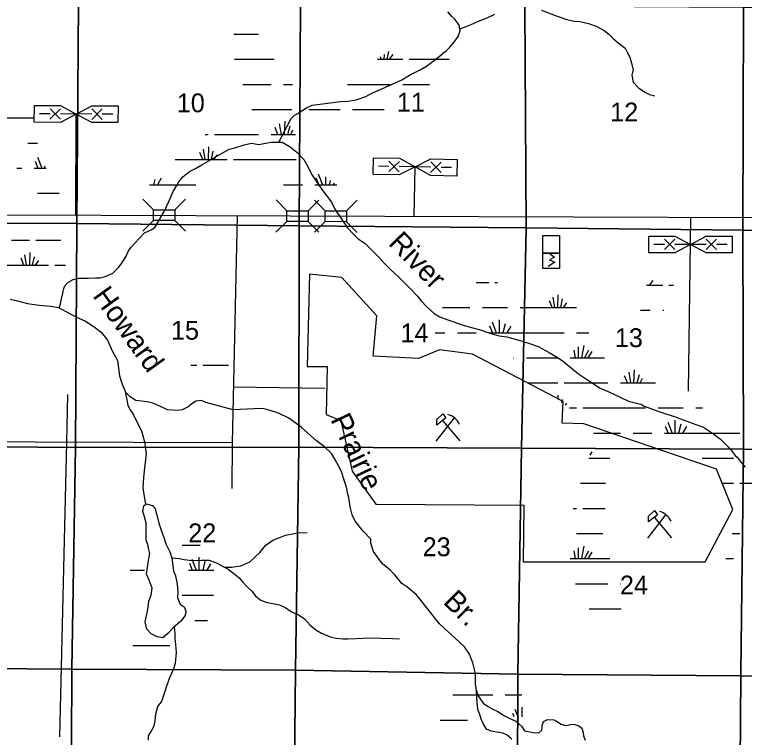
# Model space of a CAD drawing. Extents: x 380424 to 701066, y 1117407 to 1412949.
# Drawn here: x 588826 to 606273, y 1213175 to 1230454 of the extents above; entities that cross this region are included whole.
import ezdxf

# ---------------------------------------------------------------- set-up
doc = ezdxf.new("R2010")
doc.units = 0
for name, color, linetype in [('Bridges and Drawbridges State Highways', 7, 'Continuous'), ('Culture', 7, 'Continuous'), ('Intermittent Ponds', 7, 'Continuous'), ('Lakes and Ponds', 7, 'Continuous'), ('Local Roads Improved', 7, 'Continuous'), ('Local Roads Paved', 7, 'Continuous'), ('Local Roads Related Cells', 7, 'Continuous'), ('Narrow River Creek and Branch and Slough', 7, 'Continuous'), ('Narrow River Creek and Branch and Slough Text', 7, 'Continuous'), ('Section Lines', 7, 'Continuous'), ('Section Numbers', 7, 'Continuous'), ('State Routes Highway Center Lines', 7, 'Continuous'), ('Strip Mining Area', 7, 'Continuous'), ('Swamps', 7, 'Continuous'), ('Township  and Range lines', 7, 'Continuous')]:
    doc.layers.add(name, color=color, linetype=linetype)

msp = doc.modelspace()

# ---------------------------------------------------------------- linework, layer by layer
at = {"layer": 'Bridges and Drawbridges State Highways'}
for p, q in [((592146, 1225786), (591890, 1226042)), ((592658, 1225786), (592914, 1226042)), ((595332, 1225765), (595077, 1226022)), ((595844, 1225763), (596101, 1226018)), ((596250, 1225761), (595995, 1226018)), ((596762, 1225760), (597019, 1226015)), ((592146, 1225530), (591890, 1225274)), ((592658, 1225530), (592914, 1225274)), ((595331, 1225509), (595074, 1225254)), ((595843, 1225507), (596098, 1225250)), ((596249, 1225505), (595992, 1225250)), ((596761, 1225504), (597016, 1225247))]:
    msp.add_line(p, q, dxfattribs=at)
for points in [[(592146, 1225786), (592658, 1225786), (592658, 1225530), (592146, 1225530)], [(595332, 1225765), (595844, 1225763), (595843, 1225507), (595331, 1225509)], [(596250, 1225761), (596762, 1225760), (596761, 1225504), (596249, 1225505)]]:
    msp.add_lwpolyline(points, close=True, dxfattribs=at)
at = {"layer": 'Culture'}
for p, q in [((601452, 1224382), (601452, 1224753)), ((601452, 1224753), (601853, 1224753)), ((601853, 1224753), (601853, 1224382)), ((601853, 1224382), (601452, 1224382)), ((598902, 1220253), (599339, 1220812)), ((599058, 1220754), (599471, 1220261)), ((603961, 1217936), (604398, 1218495)), ((604117, 1218437), (604530, 1217944))]:
    msp.add_line(p, q, dxfattribs=at)
for points in [[(601853, 1224753), (601452, 1224753), (601452, 1225172), (601853, 1225172)], [(599064, 1220913), (599134, 1220814), (598919, 1220642), (598919, 1220777)], [(604123, 1218596), (604193, 1218497), (603978, 1218325), (603978, 1218460)]]:
    msp.add_lwpolyline(points, close=True, dxfattribs=at)
msp.add_lwpolyline([(601608, 1224753), (601729, 1224659), (601617, 1224591), (601738, 1224532), (601582, 1224432)], dxfattribs=at)
for centre in [(599068, 1220480), (604127, 1218163)]:
    msp.add_arc(centre, 431, 24.5415, 74.8304, dxfattribs=at)
at = {"layer": 'Intermittent Ponds'}
msp.add_lwpolyline([(600712, 1213137), (600602, 1213226), (600497, 1213278), (600356, 1213299), (600219, 1213325), (600109, 1213373), (600035, 1213488), (599978, 1213609), (599946, 1213724), (599899, 1213840), (599889, 1213934), (599883, 1213997), (599868, 1214302), (599878, 1214260), (599915, 1214155), (599920, 1214144), (600025, 1213992), (600130, 1213918), (600240, 1213861), (600377, 1213793), (600539, 1213688), (600649, 1213635), (600807, 1213562), (600943, 1213441), (601017, 1213336), (601221, 1213289), (601358, 1213284), (601426, 1213346), (601437, 1213394), (601437, 1213462), (601468, 1213556), (601563, 1213604), (601715, 1213598), (601778, 1213562), (601893, 1213488), (601993, 1213457), (602056, 1213467), (602119, 1213483), (602192, 1213488), (602313, 1213451), (602387, 1213399), (602418, 1213289), (602428, 1213215), (602465, 1213110)], dxfattribs=at)
at = {"layer": 'Lakes and Ponds'}
msp.add_lwpolyline([(591982, 1217081), (592029, 1217401), (592056, 1217574), (592024, 1217700), (592008, 1217789), (591972, 1217889), (591972, 1218304), (591919, 1218503), (591888, 1218587), (591919, 1218708), (591972, 1218760), (592124, 1218718), (592187, 1218640), (592239, 1218435), (592276, 1218293), (592323, 1218151), (592397, 1217957), (592439, 1217800), (592533, 1217611), (592586, 1217464), (592607, 1217286), (592628, 1217149), (592670, 1217034), (592712, 1216840), (592727, 1216656), (592722, 1216509), (592780, 1216362), (592880, 1216294), (592916, 1216194), (592906, 1216089), (592801, 1215953), (592607, 1215785), (592491, 1215659), (592371, 1215559), (592234, 1215580), (592087, 1215654), (591987, 1215764), (591945, 1215937), (592014, 1216231), (592035, 1216430), (592092, 1216572), (592113, 1216745), (592045, 1216934)], close=True, dxfattribs=at)
at = {"layer": 'Local Roads Improved'}
for points in [[(590293, 1225655), (590298, 1228076)], [(598374, 1225626), (598398, 1226813)], [(590090, 1221370), (590064, 1220229)], [(594030, 1220213), (594017, 1219124)]]:
    msp.add_lwpolyline(points, dxfattribs=at)
at = {"layer": 'Local Roads Paved'}
for points in [[(594146, 1225641), (594030, 1220213), (584600, 1220250), (584573, 1217567), (580552, 1217530), (580478, 1214990), (581912, 1214974), (581785, 1204105)], [(604933, 1221456), (604994, 1225603)], [(594058, 1221553), (596248, 1221524)], [(590064, 1220229), (589902, 1213187)]]:
    msp.add_lwpolyline(points, dxfattribs=at)
at = {"layer": 'Local Roads Related Cells'}
for p, q in [((589297, 1227881), (589299, 1228281)), ((589299, 1228281), (589924, 1228278)), ((589924, 1228278), (590298, 1228076)), ((590298, 1228076), (590674, 1228274)), ((590674, 1228274), (591299, 1228271)), ((591299, 1228271), (591297, 1227871)), ((589672, 1227954), (589923, 1228203)), ((589922, 1227953), (589673, 1228204)), ((590672, 1227949), (590923, 1228198)), ((590922, 1227950), (590673, 1228201)), ((589673, 1228079), (589423, 1228081)), ((590298, 1228076), (589922, 1227878)), ((590673, 1228074), (589923, 1228078)), ((590672, 1227874), (590298, 1228076)), ((591173, 1228072), (590923, 1228073)), ((589922, 1227878), (589297, 1227881)), ((591297, 1227871), (590672, 1227874)), ((597394, 1226633), (597402, 1227033)), ((597402, 1227033), (598027, 1227020)), ((597770, 1226701), (598025, 1226945)), ((598020, 1226696), (597775, 1226950)), ((598027, 1227020), (598398, 1226813)), ((598398, 1226813), (598777, 1227005)), ((598770, 1226681), (599025, 1226925)), ((599020, 1226678), (598775, 1226933)), ((598777, 1227005), (599402, 1226993)), ((599402, 1226993), (599394, 1226593)), ((597773, 1226825), (597523, 1226830)), ((598398, 1226813), (598019, 1226621)), ((598773, 1226805), (598023, 1226820)), ((598769, 1226606), (598398, 1226813)), ((599273, 1226795), (599023, 1226800)), ((598019, 1226621), (597394, 1226633)), ((599394, 1226593), (598769, 1226606)), ((603984, 1225160), (604609, 1225160)), ((603984, 1224760), (603984, 1225160)), ((604609, 1225160), (604984, 1224960)), ((604984, 1224960), (605359, 1225160)), ((605359, 1225160), (605984, 1225160)), ((605984, 1225160), (605984, 1224760)), ((604359, 1224960), (604109, 1224960)), ((604359, 1224835), (604609, 1225085)), ((604609, 1224835), (604359, 1225085)), ((604984, 1224960), (604609, 1224760)), ((605359, 1224960), (604609, 1224960)), ((605359, 1224760), (604984, 1224960)), ((605609, 1224837), (605359, 1225087)), ((605359, 1224835), (605609, 1225085)), ((605859, 1224960), (605609, 1224960)), ((604609, 1224760), (603984, 1224760)), ((605984, 1224760), (605359, 1224760))]:
    msp.add_line(p, q, dxfattribs=at)
at = {"layer": 'Narrow River Creek and Branch and Slough'}
for points in [[(601424, 1230559), (601771, 1230422), (602029, 1230338), (602202, 1230301), (602339, 1230286), (602549, 1230238), (602728, 1230181), (602923, 1230075), (603028, 1229986), (603133, 1229886), (603254, 1229781), (603422, 1229655), (603464, 1229571), (603533, 1229434), (603575, 1229292), (603611, 1229145), (603585, 1229003), (603617, 1228835), (603738, 1228703), (603890, 1228598), (604006, 1228540), (604132, 1228509)], [(595146, 1227404), (595436, 1227967), (595520, 1228051), (595578, 1228083), (595631, 1228114), (595804, 1228225), (595941, 1228288), (596619, 1228377), (596803, 1228382), (596992, 1228419), (597224, 1228498), (597366, 1228577), (597571, 1228666), (597691, 1228719), (597923, 1228819), (598086, 1228898), (598307, 1229034), (598391, 1229066), (598522, 1229134), (598669, 1229224), (598801, 1229318), (598895, 1229392), (599027, 1229492), (599148, 1229592), (599237, 1229686), (599327, 1229786), (599426, 1229928), (599474, 1230065), (599453, 1230202), (599348, 1230343), (599279, 1230412), (599179, 1230522)], [(599466, 1230116), (599621, 1230170), (599742, 1230217), (599915, 1230301), (600126, 1230375), (600310, 1230464)], [(589891, 1223447), (589922, 1223536), (589949, 1223662), (589980, 1223794), (590001, 1223910), (590027, 1223973), (590096, 1224052), (590227, 1224120), (590353, 1224157), (590474, 1224157), (590585, 1224157), (590758, 1224162), (590863, 1224162), (590990, 1224193), (591174, 1224272), (591310, 1224409), (591389, 1224514), (591494, 1224682), (591552, 1224809), (591610, 1224893), (591689, 1224982), (591933, 1225240), (592090, 1225312), (592180, 1225368), (592426, 1225785), (592460, 1225869), (592518, 1226001), (592565, 1226111), (592618, 1226227), (592686, 1226348), (592755, 1226453), (592849, 1226574), (593007, 1226700), (593149, 1226774), (593301, 1226863), (593522, 1226994), (593733, 1227110), (593953, 1227236), (594090, 1227268), (594311, 1227341), (594490, 1227378), (594668, 1227352), (594952, 1227404), (595226, 1227404), (595410, 1227294), (595573, 1227163), (595741, 1226994), (595841, 1226810), (595925, 1226637), (596067, 1226421), (596172, 1226274), (596277, 1226137), (596403, 1225974), (596477, 1225817), (596517, 1225758), (596787, 1225359), (596929, 1225207), (597040, 1225091), (597208, 1224986), (597534, 1224655), (597649, 1224518), (597807, 1224366), (598007, 1224182), (598301, 1223892), (598454, 1223724), (598548, 1223614), (598669, 1223477), (598853, 1223309), (598990, 1223230), (599158, 1223162), (599300, 1223120), (599526, 1223036), (599747, 1222972), (599931, 1222925), (600184, 1222841), (600410, 1222778), (600594, 1222752), (600935, 1222652), (601182, 1222578), (601340, 1222520), (601608, 1222373), (601798, 1222263), (601950, 1222158), (602139, 1222005), (602308, 1221868), (602523, 1221726), (602823, 1221521), (603017, 1221448), (603301, 1221306), (603501, 1221216), (603753, 1221148), (603801, 1221138), (603864, 1221101), (604011, 1221043), (604227, 1220964), (604421, 1220901), (604600, 1220848), (604721, 1220796), (604921, 1220728), (605115, 1220654), (605294, 1220591), (605536, 1220433), (605704, 1220302), (605846, 1220160), (605930, 1220070), (606051, 1219918), (606103, 1219871), (606193, 1219750), (606293, 1219639)], [(588722, 1223649), (588896, 1223612), (589138, 1223549), (589411, 1223507), (589695, 1223481), (589879, 1223454), (590052, 1223355), (590184, 1223281), (590363, 1223197), (590520, 1223129), (590725, 1222992), (590894, 1222860), (591046, 1222671), (591167, 1222398), (591283, 1222182), (591335, 1221819), (591398, 1221620), (591472, 1221451), (591530, 1221120), (591572, 1221031), (591666, 1220889), (591766, 1220689), (591856, 1220505), (591935, 1220240), (591973, 1219956), (591951, 1219746), (591925, 1219546), (591904, 1219378), (591894, 1219146), (591915, 1218983), (591917, 1218979), (591959, 1218747)], [(599868, 1214302), (599841, 1214454), (599841, 1214700), (599784, 1214958), (599700, 1215162), (599584, 1215341), (599348, 1215556), (599122, 1215760), (598986, 1215892), (598766, 1216165), (598535, 1216458), (598424, 1216590), (598204, 1216773), (598083, 1216857), (597915, 1217062), (597805, 1217172), (597622, 1217324), (597506, 1217477), (597406, 1217623), (597343, 1217818), (597338, 1217917), (597165, 1218096), (597097, 1218185), (596966, 1218348), (596892, 1218495), (596845, 1218684), (596813, 1218914), (596787, 1219019), (596766, 1219124), (596719, 1219277), (596630, 1219544), (596477, 1219843), (596399, 1219959), (596226, 1220132), (596042, 1220263), (595837, 1220447), (595675, 1220594), (595381, 1220809), (595134, 1220924), (594914, 1220998), (594756, 1221035), (594552, 1221029), (594052, 1221005), (593396, 1221183), (593291, 1221230), (593155, 1221210), (593055, 1221141), (592976, 1221078), (592835, 1221005), (592730, 1220989), (592483, 1221005), (592315, 1221084), (592131, 1221168), (591995, 1221194), (591859, 1221210), (591727, 1221225), (591591, 1221320), (591476, 1221427)], [(593852, 1217241), (594009, 1217247), (594235, 1217279), (594451, 1217373), (594687, 1217599), (594829, 1217773), (595003, 1217894), (595181, 1217962), (595302, 1218010), (595633, 1218073), (595823, 1218062)], [(592583, 1217471), (592756, 1217448), (592882, 1217432), (593066, 1217406), (593292, 1217416), (593476, 1217411), (593665, 1217343), (593813, 1217264), (593928, 1217196), (594070, 1217091), (594186, 1216996), (594275, 1216896), (594380, 1216786), (594501, 1216670), (594575, 1216565), (594696, 1216465), (594833, 1216407), (595158, 1216344), (595311, 1216270), (595458, 1216170), (595605, 1216113), (595753, 1216013), (595889, 1215860), (596031, 1215750), (596163, 1215666), (596368, 1215576), (596515, 1215545), (596678, 1215529), (596804, 1215529), (596993, 1215540), (597304, 1215555), (597871, 1215540), (598029, 1215534)], [(592028, 1213113), (592028, 1213212), (592091, 1213318), (592165, 1213449), (592186, 1213575), (592202, 1213738), (592249, 1213912), (592338, 1214027), (592375, 1214138), (592428, 1214280), (592464, 1214411), (592538, 1214606), (592627, 1214800), (592669, 1214947), (592696, 1215205), (592680, 1215400), (592664, 1215542), (592664, 1215662), (592649, 1215821)]]:
    msp.add_lwpolyline(points, dxfattribs=at)
at = {"layer": 'Section Lines'}
for points in [[(590354, 1230726), (590354, 1230713), (590316, 1225459), (584947, 1225482), (584988, 1230777), (590334, 1230727)], [(595661, 1230692), (595626, 1225416), (595626, 1225407), (590323, 1225459), (590316, 1225459), (590354, 1230713), (590354, 1230726)], [(601027, 1230664), (601027, 1230646), (601059, 1225354), (595626, 1225407), (595626, 1225416), (595661, 1230692), (595676, 1230692)], [(606248, 1230633), (606248, 1230626), (606236, 1225303), (601059, 1225354), (601027, 1230646), (601027, 1230664)], [(611856, 1230581), (611856, 1230571), (611837, 1225330), (611840, 1225292), (606258, 1225303), (606236, 1225303), (606248, 1230626), (606248, 1230633), (611846, 1230581)], [(590316, 1225459), (590316, 1225426), (590282, 1220107), (590268, 1220107), (584902, 1220152), (584895, 1220152), (584895, 1220166), (584946, 1225472), (584947, 1225482)], [(595626, 1225407), (595618, 1220117), (590282, 1220107), (590316, 1225426), (590316, 1225459), (590323, 1225459)], [(601059, 1225354), (601059, 1225331), (600943, 1220092), (595618, 1220117), (595626, 1225407)], [(606236, 1225303), (606236, 1225278), (606252, 1220073), (606252, 1220063), (600943, 1220092), (601059, 1225331), (601059, 1225354)], [(611840, 1225292), (611868, 1220018), (606271, 1220063), (606252, 1220063), (606252, 1220073), (606236, 1225278), (606236, 1225303), (606258, 1225303)], [(590282, 1220107), (590282, 1220103), (590192, 1214804), (584853, 1214848), (584895, 1220152), (584902, 1220152), (590268, 1220107)], [(595618, 1220117), (595543, 1214785), (590207, 1214803), (590192, 1214804), (590282, 1220103), (590282, 1220107)], [(600943, 1220092), (600854, 1214688), (600854, 1214684), (595543, 1214785), (595618, 1220117)], [(606252, 1220063), (606191, 1214707), (606191, 1214649), (600854, 1214684), (600854, 1214688), (600943, 1220092)], [(611868, 1220018), (611870, 1214702), (611870, 1214647), (608875, 1214632), (606191, 1214649), (606191, 1214707), (606252, 1220063), (606271, 1220063)], [(590192, 1214804), (590192, 1214786), (590168, 1209527), (590168, 1209522), (590161, 1209522), (584812, 1209549), (584853, 1214848)], [(595543, 1214785), (595543, 1214763), (595483, 1209507), (590168, 1209522), (590168, 1209527), (590192, 1214786), (590192, 1214804), (590207, 1214803)], [(600854, 1214684), (600837, 1209483), (595488, 1209507), (595483, 1209507), (595543, 1214763), (595543, 1214785)], [(606191, 1214649), (606147, 1209426), (600837, 1209483), (600854, 1214684)], [(611870, 1214647), (611802, 1209383), (606157, 1209426), (606147, 1209426), (606191, 1214649), (608875, 1214632)]]:
    msp.add_lwpolyline(points, close=True, dxfattribs=at)
at = {"layer": 'State Routes Highway Center Lines'}
msp.add_lwpolyline([(640551, 1225621), (608969, 1225590), (572811, 1225715), (567889, 1228370), (547875, 1228304), (542500, 1228290), (542132, 1228289), (536228, 1228275), (533934, 1228260), (532069, 1228431), (531223, 1228480), (521382, 1228594), (519319, 1228617), (515590, 1228660)], dxfattribs=at)
at = {"layer": 'Strip Mining Area'}
for p, q in [((595879, 1224248), (595816, 1222042)), ((596649, 1224167), (595879, 1224248)), ((597482, 1223251), (596649, 1224167)), ((597399, 1222292), (597482, 1223251)), ((598981, 1222438), (598481, 1222230)), ((599772, 1222334), (598981, 1222438)), ((601938, 1221209), (599772, 1222334)), ((598481, 1222230), (597399, 1222292)), ((595816, 1222042), (596295, 1222042)), ((596295, 1222042), (596274, 1220897)), ((601917, 1220688), (601938, 1221209)), ((596274, 1220897), (596628, 1220751)), ((596628, 1220751), (596899, 1219543)), ((602437, 1220668), (601917, 1220688)), ((605602, 1219584), (602437, 1220668)), ((596899, 1219543), (597461, 1218751)), ((605998, 1218626), (605602, 1219584)), ((597461, 1218751), (601001, 1218730)), ((601001, 1218730), (600980, 1217376)), ((605331, 1217376), (605998, 1218626)), ((600980, 1217376), (605331, 1217376))]:
    msp.add_line(p, q, dxfattribs=at)
at = {"layer": 'Swamps'}
for p, q in [((597792, 1229387), (597876, 1229500)), ((597357, 1228787), (597807, 1228787)), ((595857, 1228187), (596607, 1228187)), ((596907, 1228187), (597357, 1228187)), ((597357, 1228187), (597657, 1228187)), ((595122, 1227587), (595057, 1227759)), ((595207, 1227587), (595161, 1227842)), ((595278, 1227587), (595295, 1227903)), ((595355, 1227587), (595413, 1227791)), ((593607, 1227587), (594657, 1227587)), ((595431, 1227587), (595480, 1227696)), ((593385, 1226987), (593345, 1227240)), ((593463, 1226987), (593469, 1227291)), ((593322, 1226988), (593256, 1227161)), ((593530, 1226987), (593573, 1227193)), ((593592, 1226987), (593676, 1227100)), ((589314, 1226949), (589385, 1226783)), ((593157, 1226987), (593907, 1226987)), ((594057, 1226987), (595557, 1226987)), ((592333, 1226541), (592243, 1226387)), ((596026, 1226553), (596097, 1226387)), ((595257, 1226387), (595707, 1226387)), ((588884, 1225061), (589184, 1225061)), ((589049, 1224462), (588983, 1224634)), ((589112, 1224461), (589072, 1224714)), ((589190, 1224461), (589196, 1224764)), ((589257, 1224461), (589300, 1224666)), ((588884, 1224461), (589634, 1224461)), ((589319, 1224460), (589403, 1224574)), ((601816, 1223450), (601822, 1223754)), ((601738, 1223450), (601698, 1223703)), ((601883, 1223450), (601926, 1223656)), ((601945, 1223449), (602029, 1223563)), ((600010, 1223450), (600610, 1223450)), ((601510, 1223450), (602260, 1223450)), ((600239, 1223113), (600342, 1222850)), ((600408, 1223161), (600408, 1222850)), ((600553, 1223064), (600500, 1222850)), ((600179, 1223016), (600250, 1222850)), ((600686, 1223004), (600597, 1222850)), ((599410, 1222850), (599860, 1222850)), ((600160, 1222850), (601510, 1222850)), ((601510, 1222850), (601960, 1222850)), ((602301, 1222508), (602301, 1222250)), ((602434, 1222545), (602375, 1222250)), ((602192, 1222436), (602229, 1222250)), ((602542, 1222424), (602448, 1222249)), ((602627, 1222400), (602528, 1222251)), ((601060, 1222250), (601510, 1222250)), ((601510, 1222250), (601810, 1222250)), ((603475, 1221650), (603410, 1221822)), ((603560, 1221650), (603514, 1221904)), ((603631, 1221650), (603648, 1221966)), ((603708, 1221650), (603766, 1221854)), ((601510, 1221650), (601810, 1221650)), ((601960, 1221650), (603010, 1221650)), ((603784, 1221650), (603833, 1221759)), ((602410, 1221050), (603910, 1221050)), ((604210, 1221050), (604810, 1221050)), ((604379, 1220616), (604450, 1220450)), ((604439, 1220713), (604542, 1220450)), ((604608, 1220761), (604608, 1220450)), ((604753, 1220664), (604700, 1220450)), ((604886, 1220604), (604796, 1220450)), ((603610, 1220450), (604060, 1220450)), ((604360, 1220450), (605710, 1220450)), ((605710, 1220450), (606160, 1220450)), ((605260, 1219850), (605710, 1219850)), ((605710, 1219850), (606010, 1219850)), ((606160, 1219250), (607210, 1219250)), ((602192, 1217636), (602229, 1217450)), ((602301, 1217708), (602301, 1217450)), ((602434, 1217745), (602375, 1217450)), ((602542, 1217624), (602448, 1217449)), ((593232, 1217484), (593232, 1217173)), ((602627, 1217600), (602528, 1217451)), ((593003, 1217339), (593073, 1217173)), ((593063, 1217435), (593166, 1217173)), ((593377, 1217387), (593324, 1217173)), ((593510, 1217327), (593420, 1217173)), ((592834, 1216573), (593584, 1216573)), ((593134, 1215973), (593434, 1215973))]:
    msp.add_line(p, q, dxfattribs=at)
for points in [[(594069, 1229987), (594657, 1229987)], [(597663, 1229387), (597665, 1229502)], [(597730, 1229387), (597769, 1229572)], [(594081, 1229387), (595028, 1229387)], [(597502, 1229387), (598107, 1229387)], [(597522, 1229388), (597518, 1229400)], [(597585, 1229387), (597576, 1229442)], [(598257, 1229387), (599218, 1229387)], [(594282, 1228787), (594957, 1228787)], [(595257, 1228787), (595472, 1228787)], [(596784, 1228787), (597357, 1228787)], [(598107, 1228787), (598747, 1228787)], [(594495, 1228187), (595457, 1228187)], [(588568, 1227983), (589295, 1227983)], [(593385, 1227587), (593457, 1227587)], [(594957, 1227587), (595540, 1227587)], [(589145, 1227383), (589371, 1227383)], [(589375, 1227046), (589478, 1226783)], [(592662, 1226987), (593157, 1226987)], [(588878, 1226783), (588995, 1226783)], [(589295, 1226783), (589577, 1226783)], [(589544, 1226833), (589544, 1226783)], [(596086, 1226650), (596189, 1226387)], [(596255, 1226572), (596255, 1226387)], [(592050, 1226387), (593157, 1226387)], [(592055, 1226392), (592055, 1226387)], [(592178, 1226514), (592147, 1226387)], [(596007, 1226387), (596527, 1226387)], [(596373, 1226492), (596347, 1226387)], [(596467, 1226428), (596443, 1226387)], [(589373, 1226183), (589895, 1226183)], [(588751, 1225061), (588884, 1225061)], [(589334, 1225061), (589929, 1225061)], [(588624, 1224461), (588884, 1224461)], [(589784, 1224461), (590040, 1224461)], [(604005, 1223986), (604088, 1224099)], [(599857, 1224050), (600160, 1224050)], [(600310, 1224050), (600371, 1224050)], [(603940, 1223986), (604319, 1223986)], [(603942, 1223986), (603944, 1223991)], [(604469, 1223986), (604574, 1223986)], [(601675, 1223451), (601614, 1223611)], [(599059, 1223450), (599710, 1223450)], [(600910, 1223450), (601443, 1223450)], [(601457, 1223450), (601510, 1223450)], [(603790, 1223386), (604019, 1223386)], [(604319, 1223386), (604347, 1223386)], [(598882, 1222850), (599110, 1222850)], [(602260, 1222850), (602553, 1222850)], [(600749, 1222250), (600760, 1222250)], [(602110, 1222250), (602929, 1222250)], [(593040, 1222076), (593179, 1222076)], [(593329, 1222076), (593941, 1222076)], [(601093, 1221650), (601510, 1221650)], [(603310, 1221650), (604145, 1221650)], [(601820, 1221252), (601822, 1221354)], [(601910, 1221181), (601926, 1221256)], [(601996, 1221119), (602029, 1221163)], [(602090, 1221050), (602260, 1221050)], [(605110, 1221050), (605274, 1221050)], [(602663, 1220450), (603310, 1220450)], [(602627, 1220000), (602574, 1219920)], [(602551, 1219850), (603052, 1219850)], [(602355, 1219250), (602953, 1219250)], [(605751, 1219250), (606010, 1219250)], [(602181, 1218650), (602260, 1218650)], [(602410, 1218650), (602941, 1218650)], [(602260, 1218050), (602891, 1218050)], [(605978, 1218050), (606160, 1218050)], [(592834, 1217773), (593262, 1217773)], [(602110, 1217450), (603056, 1217450)], [(605827, 1217450), (606010, 1217450)], [(591588, 1217173), (591934, 1217173)], [(592984, 1217173), (593591, 1217173)], [(602231, 1216850), (603010, 1216850)], [(603310, 1216850), (603321, 1216850)], [(602565, 1216250), (603324, 1216250)], [(591649, 1215373), (592534, 1215373)], [(599301, 1214189), (600255, 1214189)], [(600555, 1214189), (600948, 1214189)], [(600785, 1213852), (600863, 1213652)], [(600954, 1213900), (600954, 1213667)], [(600725, 1213755), (600760, 1213671)], [(599003, 1213589), (599655, 1213589)]]:
    msp.add_lwpolyline(points, dxfattribs=at)
at = {"layer": 'Township  and Range lines'}
for p, q in [((606248, 1230626), (606236, 1225303)), ((606236, 1225303), (606236, 1225278)), ((606236, 1225278), (606252, 1220073)), ((606252, 1220063), (606191, 1214707)), ((606252, 1220073), (606252, 1220063)), ((606191, 1214707), (606191, 1214649)), ((606191, 1214649), (606147, 1209427))]:
    msp.add_line(p, q, dxfattribs=at)

# ---------------------------------------------------------------- texts
at = {"layer": 'Narrow River Creek and Branch and Slough Text'}
for s, rotation, p in [('River', 314.1448, (597740, 1224971)), ('Howard', 305.7701, (590677, 1223728)), ('Prairie', 295.4441, (596366, 1220773)), ('Br.', 315.4441, (599048, 1216393))]:
    msp.add_text(s, height=500, rotation=rotation, dxfattribs=at).set_placement(p)
at = {"layer": 'Section Numbers'}
for s, rotation, p in [('10', 0.0003, (592703, 1228119)), ('11', 0.0003, (597965, 1228135)), ('12', 0.0003, (603065, 1227900)), ('15', 0.0003, (592564, 1222683)), ('14', 0.0003, (598051, 1222620)), ('13', 0.0003, (603176, 1222505)), ('22', 0.0002, (592978, 1217841)), ('23', 0.0002, (598581, 1217507)), ('24', 0.0002, (603297, 1216593))]:
    msp.add_text(s, height=450, rotation=rotation, dxfattribs=at).set_placement(p)

doc.saveas('drawing.dxf')
